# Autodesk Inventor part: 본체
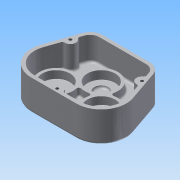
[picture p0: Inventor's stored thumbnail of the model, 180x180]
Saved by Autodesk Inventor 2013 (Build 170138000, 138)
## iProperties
Created: 2014-12
Part Number: 본체
Material: 알루미늄 6061
Document SubType Name: Modeling
Designer: Administrator
Density: 2.71 g/cm^3
Mass: 596.952 g
Surface Area: 670.328 cm^2
Volume: 220.278 cm^3
Author: Administrator
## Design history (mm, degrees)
sketch "스케치1"
  geometry: L1 (-32.527, -68.527)-(32.527, -68.527); L2 (-67.006, -22.085)-(-47, 36); L3 (-47, 36)-(47, 36); L4 (47, 36)-(67.006, -22.085); L5 (-32.527, -32.527)-(0, 0); L6 (0, 0)-(32.527, -32.527); A1 r 36 centre (-32.527, -32.527) between (-66.565, -20.803) and (-32.527, -68.527); A2 r 36 centre (32.527, -32.527) between (32.527, -68.527) and (66.565, -20.803); 1 further point
  constraints: 12 end point, 4 point on circle, 3 tangent, 2 centre point, 2 coincident, 2 point on line, 1 equal length, 1 horizontal, 1 horizontal alignment, 1 midpoint, 1 parallel, 1 vertical alignment
  dimensions: "d4" = 36 distance of L5.end point (0, 36); "d5" = 94 distance of L2.end L3.end; "d6" = 46 distance of L5.end L5.start; "d7" = 46 distance of L5.end L6.end; "d72" = 90 deg angle of L6 L5; "d73" = 72 diameter of A1; "d75" = 36 radius of A2
extrude "돌출1" new body sketch "스케치1" distance "d8" = 44; taper "d9" = 0 deg
fillet "모깎기1" dims "d13" = 18
sketch "스케치15"
  geometry: L1 (34.162, 36)-(-34.162, 36) reference; L2 (-51.181, 23.862)-(-66.565, -20.803) reference; L3 (-32.527, -68.527)-(32.527, -68.527) reference; L4 (66.565, -20.803)-(51.181, 23.862) reference; L5 (-34.162, 31)-(34.162, 31); L6 (46.453, 22.233)-(61.837, -22.432); L7 (32.527, -63.527)-(-32.527, -63.527); L8 (-61.837, -22.432)-(-46.453, 22.233); A1 r 18 centre (34.162, 18) between (51.181, 23.862) and (34.162, 36) reference; A2 r 18 centre (-34.162, 18) between (-34.162, 36) and (-51.181, 23.862) reference; A3 r 36 centre (-32.527, -32.527) between (-66.565, -20.803) and (-32.527, -68.527) reference; A4 r 36 centre (32.527, -32.527) between (32.527, -68.527) and (66.565, -20.803) reference; A5 r 13 centre (34.162, 18) between (46.453, 22.233) and (34.162, 31); A6 r 31 centre (32.527, -32.527) between (32.527, -63.527) and (61.837, -22.432); A7 r 31 centre (-32.527, -32.527) between (-61.837, -22.432) and (-32.527, -63.527); A8 r 13 centre (-34.162, 18) between (-34.162, 31) and (-46.453, 22.233); 1 further point
  constraints: 8 end point, 8 point on circle, 4 centre point, 7 other
  dimensions: "d76" = 5 distance between parallel lines of L1 L5
extrude "돌출12" cut sketch "스케치15" distance "d77" = 34; taper "d78" = 0 deg
sketch "스케치16"
  geometry: C1 r 24 at (0, 0); C2 r 24 at (-32.527, -32.527); C3 r 24 at (32.527, -32.527); A1 r 31 centre (-32.527, -32.527) between (-61.837, -22.432) and (-32.527, -63.527) reference; A2 r 31 centre (32.527, -32.527) between (32.527, -63.527) and (61.837, -22.432) reference; 1 further point
  constraints: 3 centre point, 3 coincident
  dimensions: "d79" = 48 diameter of C1; "d80" = 48 diameter of C2; "d81" = 48 diameter of C3
extrude "돌출13" join sketch "스케치16" distance "d82" = 11; taper "d83" = 0 deg
sketch "스케치17"
  geometry: C1 r 20 at (0, 0); A1 r 24 centre (0, 0) between (21.111, -11.416) and (-21.111, -11.416) reference
  constraints: 1 centre point, 1 coincident
  dimensions: "d84" = 40 diameter of C1
extrude "돌출14" cut sketch "스케치17" distance "d85" = 12; taper "d86" = 0 deg
sketch "스케치18"
  geometry: C1 r 20 at (-32.527, -32.527); C2 r 20 at (32.527, -32.527); A1 r 24 centre (32.527, -32.527) between (11.416, -21.111) and (21.111, -11.416) reference; A2 r 24 centre (-32.527, -32.527) between (-21.111, -11.416) and (-11.416, -21.111) reference
  constraints: 2 centre point, 2 coincident
  dimensions: "d87" = 40 diameter of C1; "d88" = 40 diameter of C2
extrude "돌출15" cut sketch "스케치18" distance "d89" = 11; taper "d90" = 0 deg
sketch "스케치19"
  geometry: C1 r 20 at (-32.527, -32.527); C2 r 20 at (32.527, -32.527); A1 r 36 centre (-32.527, -32.527) between (-66.565, -20.803) and (-32.527, -68.527) reference; A2 r 36 centre (32.527, -32.527) between (32.527, -68.527) and (66.565, -20.803) reference; 1 further point
  constraints: 2 centre point, 2 coincident
  dimensions: "d91" = 40 diameter of C1; "d92" = 40 diameter of C2
extrude "돌출16" join sketch "스케치19" distance "d93" = 7; taper "d94" = -10 deg
sketch "스케치20"
  geometry: C1 r 18.766 at (0, 0) reference; C2 r 18.766 at (65.054, 0) reference; 3 further points
  constraints: 2 coincident
hole "구멍2" sketch "스케치20" at (0, 0), (65.054, 0) diameter "d95" = 15.5; stored, may be unused: countersink angle "d99" = 90 deg, drill point angle "d101" = 118 deg; dims "d96" = 6, "d97" = 30, "d98" = 7, "d100" = 8
sketch "스케치21"
  geometry: C1 r 20 at (0, 0) reference; C2 r 10 at (0, 0)
  constraints: 1 centre point, 1 coincident
  dimensions: "d102" = 20 diameter of C2
extrude "돌출17" cut sketch "스케치21" distance "d103" = 3; taper "d104" = 0 deg
sketch "스케치22"
  geometry: L1 (-34.162, 36)-(34.162, 36) reference; 2 further points
  constraints: 1 vertical alignment, 1 other
  dimensions: "d105" = 30 distance from line of L1 point (0, 6)
feature "엠보싱2" sketch "스케치22" dims "d4" = 36, "d5" = 94, "d6" = 46, "d7" = 46, "d72" = 90 deg, "d73" = 72, "d75" = 36, "d106" = 1, "d107" = 0
sketch "스케치23"
  geometry: L1 (46.453, 22.233)-(61.837, -22.432) reference; L2 (32.527, -63.527)-(-32.527, -63.527) reference; L3 (-61.837, -22.432)-(-46.453, 22.233) reference; L4 (34.162, 36)-(-34.162, 36) reference; A1 r 8 centre (-51.7, 7) between (-54.305, -0.564) and (-49.095, 14.564); A2 r 8 centre (51.7, 7) between (49.095, 14.564) and (54.305, -0.564); A3 r 8 centre (0, -63.527) between (8, -63.527) and (-8, -63.527); 1 further point
  constraints: 8 point on line, 6 point on circle, 3 centre point, 1 horizontal alignment, 1 midpoint
  dimensions: "d108" = 16 diameter of A1; "d109" = 16 diameter of A2; "d110" = 16 diameter of A3; "d111" = 29 distance from line of L4 A1.centre
extrude "돌출18" join sketch "스케치23" stored distance "d112" = 3; taper "d113" = 0 deg
sketch "스케치24"
  geometry: A1 r 8 centre (0, -63.527) between (8, -63.527) and (-8, -63.527) reference; A2 r 8 centre (-51.7, 7) between (-54.305, -0.564) and (-49.095, 14.564) reference; A3 r 8 centre (51.7, 7) between (49.095, 14.564) and (54.305, -0.564) reference; 4 further points
  constraints: 3 coincident
hole "구멍3" sketch "스케치24" at (-51.7, 7), (0, -63.527), (51.7, 7) diameter "d114" = 4.134; stored, may be unused: countersink angle "d118" = 90 deg, drill point angle "d120" = 118 deg; dims "d115" = 13, "d116" = 30, "d117" = 7, "d119" = 20
fillet "모깎기5" dims "d121" = 3
fillet "모깎기6" dims "d122" = 3
fillet "모깎기7" dims "d123" = 3
fillet "모깎기8" dims "d124" = 3
fillet "모깎기9" dims "d125" = 3
fillet "모깎기10" dims "d126" = 0.3
fillet "모깎기11" dims "d127" = 3
fillet "모깎기12" dims "d128" = 0.3
fillet "모깎기13" dims "d129" = 3
node "솔리드1"
node "투영된 루프3"
other parameters: "d74" = 72
